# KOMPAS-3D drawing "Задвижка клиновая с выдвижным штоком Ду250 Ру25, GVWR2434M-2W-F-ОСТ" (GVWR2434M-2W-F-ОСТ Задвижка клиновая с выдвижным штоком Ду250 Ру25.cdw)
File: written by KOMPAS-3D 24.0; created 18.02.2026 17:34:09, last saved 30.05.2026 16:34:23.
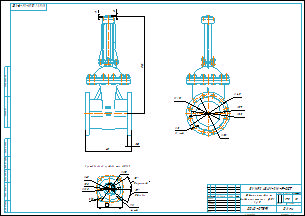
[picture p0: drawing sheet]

Document properties: Автор: R2D2; Форматы листов документа: A2; Полное имя файла: GVWR2434M-2W-F-ОСТ Задвижка клиновая с выдвижным штоком Ду250 Ру25.m3d; Масса: 175; Наименование: Задвижка клиновая с выдвижным штоком Ду250 Ру25; Количество листов документа: 1; Примечание: D040-07591

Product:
- Part/product: Задвижка клиновая с выдвижным штоком Ду250 Ру25  | designation GVWR2434M-2W-F-ОСТ
    Масса: 175
    Раздел спецификации: Прочие изделия
    Примечание: D040-07591

Views: Проекционный вид 2
Referenced files in E:\Работа\Зайцев\Для компаса\: чертеж DN.ru А3.cdt
Referenced files in E:\Работа\Зайцев\GVWR2434M-2W-F-ОСТ Задвижка клиновая с выдвижным штоком DN.ru Ду50-300 Ру25\исходные материалы\DN250\DN250\: GVWR2434M-2W-F-ОСТ Задвижка клиновая с выдвижным штоком Ду250 Ру25.m3d
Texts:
  Присоединение привода тип АК (Б)
  чертеж DN.ru А3.cdt
  Задвижка клиновая с
  выдвижным штоком Ду250
  Ру25
  GVWR2434M-2W-F-ОСТ
  Задвижка клиновая с выдвижным штоком Ду250 Ру25
  GVWR2434M-2W-F-ОСТ Задвижка клиновая с выдвижным штоком Ду250 Ру25
Dimensions and other numbers on the sheet: 108; 45; 58; 135; 13; 12; 4 отв.; 122; 5 впадин; 5 кулачков; 1:5; 0; 1; 2; 175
